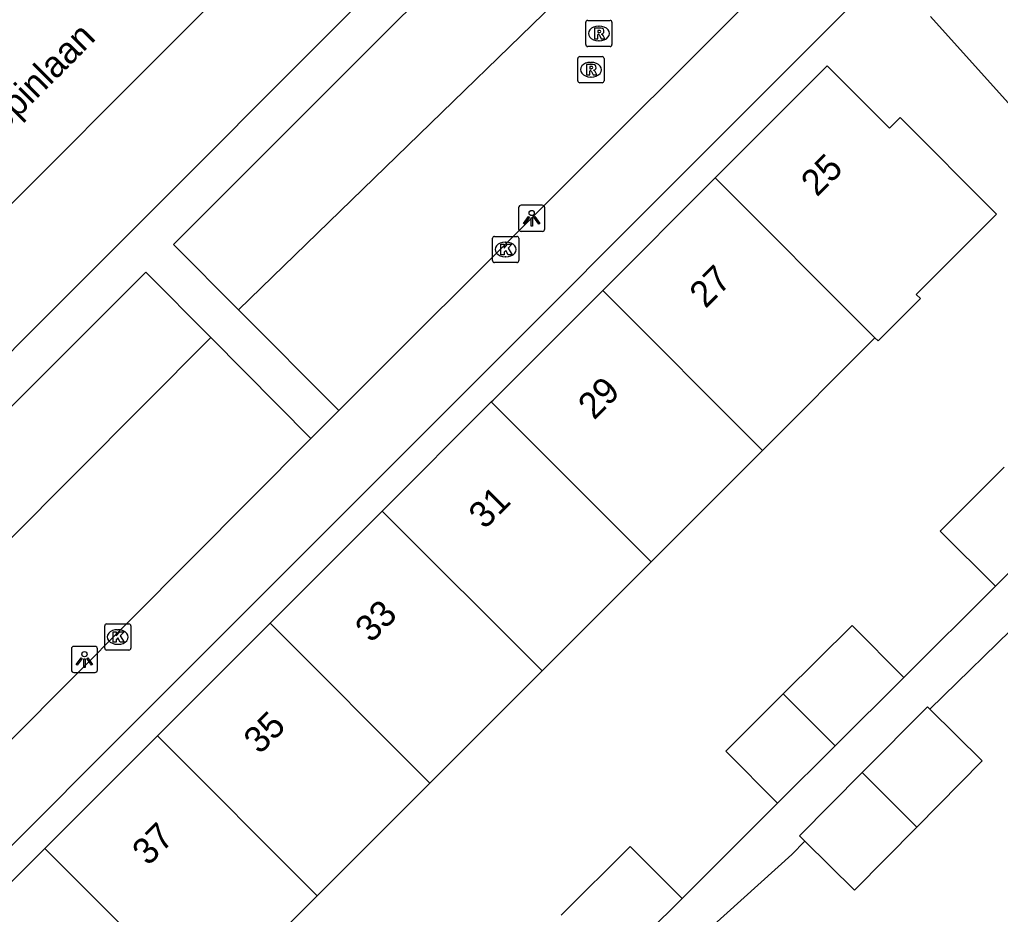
# Model space of a CAD drawing. Extents: x 159040 to 160094, y 381214 to 382518.
# Drawn here: x 159596.64 to 159634.1, y 381850.45 to 381884.61 of the extents above; entities that cross this region are included whole.
import ezdxf

# ---------------------------------------------------------------- set-up
doc = ezdxf.new("R2010")
doc.units = 0
for name, color, linetype in [('IMGEO_Groenvoorziening', 7, 'Continuous'), ('IMGEO_Kolk', 7, 'Continuous'), ('IMGEO_Lichtpunt', 7, 'Continuous'), ('IMGEO_Openbare_ruimte_label', 7, 'Continuous'), ('IMGEO_Pand', 7, 'Continuous'), ('IMGEO_Pand_nummerreeks', 7, 'Continuous'), ('IMGEO_Rijbaan_lokaal_open', 7, 'Continuous'), ('IMGEO_Rioolput', 7, 'Continuous'), ('IMGEO_Voetpad_open', 7, 'Continuous')]:
    doc.layers.add(name, color=color, linetype=linetype)

msp = doc.modelspace()

# ---------------------------------------------------------------- linework, layer by layer
at = {"layer": 'IMGEO_Groenvoorziening'}
for points in [[(159604.997, 381873.534), (159623.542, 381891.545)], [(159603.938, 381872.48), (159585.786, 381854.246)]]:
    msp.add_lwpolyline(points, dxfattribs=at)
at = {"layer": 'IMGEO_Kolk'}
for p, q in [((159614.699, 381875.411), (159614.699, 381876.263)), ((159614.774, 381876.337), (159615.626, 381876.337)), ((159615.187, 381876.117), (159615.212, 381876.117)), ((159615.7, 381876.263), (159615.7, 381875.411)), ((159615.626, 381875.337), (159614.774, 381875.337)), ((159615.21, 381875.557), (159615.185, 381875.557)), ((159599.887, 381860.615), (159599.887, 381861.467)), ((159599.962, 381861.541), (159600.814, 381861.541)), ((159600.888, 381861.467), (159600.888, 381860.615)), ((159600.375, 381861.321), (159600.4, 381861.321)), ((159600.398, 381860.761), (159600.373, 381860.761)), ((159600.814, 381860.541), (159599.962, 381860.541))]:
    msp.add_line(p, q, dxfattribs=at)
for points in [[(159614.699, 381875.411), (159614.699, 381876.263)], [(159614.774, 381876.337), (159615.626, 381876.337)], [(159615.7, 381876.263), (159615.7, 381875.411)], [(159615.02, 381876.037), (159615.143, 381876.037), (159615.143, 381875.886), (159615.273, 381876.037), (159615.437, 381876.037), (159615.291, 381875.886), (159615.444, 381875.637), (159615.292, 381875.637), (159615.207, 381875.801), (159615.143, 381875.734), (159615.143, 381875.637), (159615.02, 381875.637), (159615.02, 381876.037)], [(159615.626, 381875.337), (159614.774, 381875.337)], [(159599.887, 381860.615), (159599.887, 381861.467)], [(159599.962, 381861.541), (159600.814, 381861.541)], [(159600.888, 381861.467), (159600.888, 381860.615)], [(159600.208, 381861.241), (159600.331, 381861.241), (159600.331, 381861.09), (159600.461, 381861.241), (159600.625, 381861.241), (159600.479, 381861.09), (159600.632, 381860.841), (159600.48, 381860.841), (159600.395, 381861.005), (159600.331, 381860.938), (159600.331, 381860.841), (159600.208, 381860.841), (159600.208, 381861.241)], [(159600.814, 381860.541), (159599.962, 381860.541)]]:
    msp.add_lwpolyline(points, dxfattribs=at)
for centre, start, end in [((159614.776, 381876.261), 91.552, 178.448), ((159614.776, 381876.261), 91.552, 178.448), ((159615.624, 381876.261), 1.552, 88.448), ((159615.624, 381876.261), 1.552, 88.448), ((159614.776, 381875.413), 181.552, 268.448), ((159614.776, 381875.413), 181.552, 268.448), ((159615.624, 381875.413), 271.552, 358.448), ((159615.624, 381875.413), 271.552, 358.448), ((159599.964, 381861.465), 91.552, 178.448), ((159599.964, 381861.465), 91.552, 178.448), ((159600.812, 381861.465), 1.552, 88.448), ((159600.812, 381861.465), 1.552, 88.448), ((159599.964, 381860.617), 181.552, 268.448), ((159599.964, 381860.617), 181.552, 268.448), ((159600.812, 381860.617), 271.552, 358.448), ((159600.812, 381860.617), 271.552, 358.448)]:
    msp.add_arc(centre, 0.0765, start, end, dxfattribs=at)
for centre, major_axis, ratio, start_param, end_param in [((159615.186, 381875.837), (-0.387, 0.002), 0.722429, 4.712389, 7.853982), ((159615.211, 381875.837), (-0.39, 0.002), 0.717154, 1.570796, 4.712389), ((159600.374, 381861.041), (-0.387, 0.002), 0.722429, 4.712389, 7.853982), ((159600.399, 381861.041), (-0.39, 0.002), 0.717154, 1.570796, 4.712389)]:
    msp.add_ellipse(centre, major_axis=major_axis, ratio=ratio, start_param=start_param, end_param=end_param, dxfattribs=at)
at = {"layer": 'IMGEO_Lichtpunt'}
for p, q in [((159615.697, 381877.431), (159615.697, 381876.624)), ((159615.697, 381877.431), (159615.697, 381876.624)), ((159616.599, 381877.526), (159615.791, 381877.526)), ((159616.599, 381877.526), (159615.791, 381877.526)), ((159616.693, 381876.624), (159616.693, 381877.431)), ((159616.693, 381876.624), (159616.693, 381877.431)), ((159615.791, 381876.53), (159616.599, 381876.53)), ((159615.791, 381876.53), (159616.599, 381876.53)), ((159598.615, 381860.588), (159598.615, 381859.781)), ((159598.615, 381860.588), (159598.615, 381859.781)), ((159599.517, 381860.683), (159598.709, 381860.683)), ((159599.517, 381860.683), (159598.709, 381860.683)), ((159599.611, 381859.781), (159599.611, 381860.588)), ((159599.611, 381859.781), (159599.611, 381860.588)), ((159598.709, 381859.687), (159599.517, 381859.687)), ((159598.709, 381859.687), (159599.517, 381859.687))]:
    msp.add_line(p, q, dxfattribs=at)
for points in [[(159616.071, 381877.095), (159616.11, 381877.067), (159615.922, 381876.805), (159615.884, 381876.832), (159616.071, 381877.095)], [(159616.173, 381877.047), (159616.22, 381877.047), (159616.22, 381876.725), (159616.173, 381876.725), (159616.173, 381877.047)], [(159616.283, 381877.067), (159616.321, 381877.094), (159616.508, 381876.832), (159616.469, 381876.804), (159616.283, 381877.067)], [(159598.989, 381860.252), (159599.028, 381860.224), (159598.84, 381859.962), (159598.802, 381859.989), (159598.989, 381860.252)], [(159599.091, 381860.204), (159599.138, 381860.204), (159599.138, 381859.882), (159599.091, 381859.882), (159599.091, 381860.204)], [(159599.201, 381860.224), (159599.239, 381860.251), (159599.426, 381859.989), (159599.387, 381859.961), (159599.201, 381860.224)]]:
    msp.add_lwpolyline(points, dxfattribs=at)
for centre in [(159616.196, 381877.229), (159599.114, 381860.386)]:
    msp.add_circle(centre, 0.0994, dxfattribs=at)
for centre, start, end in [((159615.791, 381877.431), 90, 180), ((159615.791, 381877.431), 90, 180), ((159616.599, 381877.431), 0, 90), ((159616.599, 381877.431), 0, 90), ((159615.791, 381876.624), 180, 270), ((159615.791, 381876.624), 180, 270), ((159616.599, 381876.624), 270, 0), ((159616.599, 381876.624), 270, 360), ((159598.709, 381860.588), 90, 180), ((159598.709, 381860.588), 90, 180), ((159599.517, 381860.588), 0, 90), ((159599.517, 381860.588), 0, 90), ((159598.709, 381859.781), 180, 270), ((159598.709, 381859.781), 180, 270), ((159599.517, 381859.781), 270, 0), ((159599.517, 381859.781), 270, 360)]:
    msp.add_arc(centre, 0.0946, start, end, dxfattribs=at)
at = {"layer": 'IMGEO_Pand'}
for points in [[(159629.306, 381872.467), (159629.424, 381872.349), (159631.04, 381873.966), (159630.883, 381874.124), (159633.948, 381877.189), (159630.266, 381880.87), (159629.863, 381880.468), (159627.484, 381882.847), (159623.205, 381878.568)], [(159623.205, 381878.568), (159618.907, 381874.269)], [(159629.306, 381872.467), (159623.205, 381878.568)], [(159614.653, 381870.015), (159614.724, 381870.086), (159618.907, 381874.269)], [(159618.907, 381874.269), (159625.008, 381868.168)], [(159625.008, 381868.168), (159629.306, 381872.467)], [(159610.485, 381865.847), (159614.653, 381870.015)], [(159620.755, 381863.916), (159620.563, 381864.105), (159614.653, 381870.015)], [(159625.008, 381868.168), (159620.755, 381863.916)], [(159633.907, 381862.977), (159631.799, 381865.084), (159634.244, 381867.529)], [(159606.205, 381861.567), (159610.485, 381865.847)], [(159616.593, 381859.753), (159610.485, 381865.847)], [(159636.351, 381865.422), (159633.907, 381862.977)], [(159620.755, 381863.916), (159616.593, 381859.753)], [(159606.205, 381861.567), (159601.901, 381857.263)], [(159612.299, 381855.46), (159606.205, 381861.567)], [(159625.802, 381858.866), (159628.436, 381861.486), (159630.41, 381859.5)], [(159616.593, 381859.753), (159612.299, 381855.46)], [(159630.41, 381859.5), (159627.781, 381856.887)], [(159625.582, 381854.699), (159623.608, 381856.684), (159625.802, 381858.866)], [(159627.781, 381856.887), (159625.802, 381858.866)], [(159631.407, 381858.281), (159631.307, 381858.38), (159628.821, 381855.866)], [(159630.906, 381853.783), (159633.403, 381856.307), (159631.407, 381858.281)], [(159597.604, 381852.966), (159597.675, 381853.037), (159601.83, 381857.192), (159601.901, 381857.263)], [(159601.901, 381857.263), (159608.002, 381851.162)], [(159627.781, 381856.887), (159625.582, 381854.699)], [(159628.821, 381855.866), (159626.428, 381853.446), (159626.627, 381853.249)], [(159628.821, 381855.866), (159628.972, 381855.715), (159630.906, 381853.783)], [(159608.002, 381851.162), (159612.299, 381855.46)], [(159626.627, 381853.249), (159628.524, 381851.374), (159630.906, 381853.783)], [(159593.404, 381848.766), (159597.604, 381852.966)], [(159603.712, 381846.872), (159603.514, 381847.056), (159597.604, 381852.966)], [(159617.325, 381850.424), (159619.962, 381853.047), (159621.936, 381851.062)], [(159608.002, 381851.162), (159603.712, 381846.872)], [(159621.936, 381851.062), (159619.302, 381848.442)]]:
    msp.add_lwpolyline(points, dxfattribs=at)
at = {"layer": 'IMGEO_Rijbaan_lokaal_open'}
msp.add_lwpolyline([(159606.476, 381887.753), (159577.251, 381858.509)], dxfattribs=at)
at = {"layer": 'IMGEO_Rioolput'}
for p, q in [((159618.26, 381883.659), (159618.26, 381884.511)), ((159618.335, 381884.585), (159619.187, 381884.585)), ((159618.748, 381884.365), (159618.773, 381884.365)), ((159619.261, 381884.511), (159619.261, 381883.659)), ((159619.187, 381883.585), (159618.335, 381883.585)), ((159618.771, 381883.805), (159618.746, 381883.805)), ((159618.032, 381883.202), (159618.884, 381883.202)), ((159617.957, 381882.276), (159617.957, 381883.128)), ((159618.445, 381882.982), (159618.47, 381882.982)), ((159618.958, 381883.128), (159618.958, 381882.276)), ((159618.884, 381882.202), (159618.032, 381882.202)), ((159618.468, 381882.422), (159618.443, 381882.422))]:
    msp.add_line(p, q, dxfattribs=at)
for points in [[(159618.26, 381883.659), (159618.26, 381884.511)], [(159618.335, 381884.585), (159619.187, 381884.585)], [(159619.261, 381884.511), (159619.261, 381883.659)], [(159618.849, 381884.283), (159618.597, 381884.285), (159618.597, 381883.885)], [(159618.597, 381883.885), (159618.721, 381883.885), (159618.721, 381884.047), (159618.732, 381884.047)], [(159618.775, 381884.204), (159618.721, 381884.204), (159618.721, 381884.123)], [(159618.721, 381884.123), (159618.773, 381884.123)], [(159618.779, 381884.018), (159618.85, 381883.885), (159618.99, 381883.885), (159618.925, 381884.011)], [(159619.187, 381883.585), (159618.335, 381883.585)], [(159618.032, 381883.202), (159618.884, 381883.202)], [(159617.957, 381882.276), (159617.957, 381883.128)], [(159618.546, 381882.9), (159618.294, 381882.902), (159618.294, 381882.502)], [(159618.472, 381882.821), (159618.418, 381882.821), (159618.418, 381882.74)], [(159618.958, 381883.128), (159618.958, 381882.276)], [(159618.294, 381882.502), (159618.418, 381882.502), (159618.418, 381882.664), (159618.429, 381882.664)], [(159618.418, 381882.74), (159618.47, 381882.74)], [(159618.476, 381882.635), (159618.547, 381882.502), (159618.687, 381882.502), (159618.622, 381882.628)], [(159618.884, 381882.202), (159618.032, 381882.202)]]:
    msp.add_lwpolyline(points, dxfattribs=at)
for centre, radius, start, end in [((159618.337, 381884.509), 0.0765, 91.552, 178.448), ((159618.337, 381884.509), 0.0765, 91.552, 178.448), ((159619.185, 381884.509), 0.0765, 1.552, 88.448), ((159619.185, 381884.509), 0.0765, 1.552, 88.448), ((159618.731, 381883.994), 0.0533, 26.0293, 88.6989), ((159618.757, 381884.312), 0.19, 274.7715, 282.9687), ((159618.781, 381884.108), 0.0964, 77.0061, 93.1865), ((159618.795, 381884.165), 0.0378, 276.6634, 79.6772), ((159618.848, 381884.173), 0.109, 350.3612, 89.416), ((159618.846, 381884.173), 0.112, 277.5842, 350.9817), ((159618.83, 381883.958), 0.108, 29.5134, 73.7905), ((159618.337, 381883.661), 0.0765, 181.552, 268.448), ((159618.337, 381883.661), 0.0765, 181.552, 268.448), ((159619.185, 381883.661), 0.0765, 271.552, 358.448), ((159619.185, 381883.661), 0.0765, 271.552, 358.448), ((159618.034, 381883.126), 0.0765, 91.552, 178.448), ((159618.034, 381883.126), 0.0765, 91.552, 178.448), ((159618.882, 381883.126), 0.0765, 1.552, 88.448), ((159618.882, 381883.126), 0.0765, 1.552, 88.448), ((159618.478, 381882.725), 0.0964, 77.0061, 93.1865), ((159618.492, 381882.782), 0.0378, 276.6634, 79.6772), ((159618.545, 381882.79), 0.109, 350.3612, 89.416), ((159618.428, 381882.611), 0.0533, 26.0293, 88.6989), ((159618.454, 381882.929), 0.19, 274.7715, 282.9687), ((159618.543, 381882.79), 0.112, 277.5842, 350.9817), ((159618.527, 381882.575), 0.108, 29.5134, 73.7905), ((159618.034, 381882.278), 0.0765, 181.552, 268.448), ((159618.034, 381882.278), 0.0765, 181.552, 268.448), ((159618.882, 381882.278), 0.0765, 271.552, 358.448), ((159618.882, 381882.278), 0.0765, 271.552, 358.448)]:
    msp.add_arc(centre, radius, start, end, dxfattribs=at)
for centre, major_axis, ratio, start_param, end_param in [((159618.747, 381884.085), (-0.387, 0.002), 0.722429, 4.712389, 7.853982), ((159618.772, 381884.085), (-0.39, 0.002), 0.717154, 1.570796, 4.712389), ((159618.444, 381882.702), (-0.387, 0.002), 0.722429, 4.712389, 7.853982), ((159618.469, 381882.702), (-0.39, 0.002), 0.717154, 1.570796, 4.712389)]:
    msp.add_ellipse(centre, major_axis=major_axis, ratio=ratio, start_param=start_param, end_param=end_param, dxfattribs=at)
at = {"layer": 'IMGEO_Voetpad_open'}
for points in [[(159620.154, 381893.672), (159620.13, 381893.646), (159602.517, 381876.025), (159604.997, 381873.534)], [(159583.589, 381859.199), (159617.794, 381893.446)], [(159624.784, 381885.626), (159608.831, 381869.683)], [(159583.549, 381850.107), (159588.472, 381845.228), (159628.214, 381884.971)], [(159631.433, 381884.728), (159640.914, 381874.2)], [(159584.054, 381857.571), (159601.461, 381874.976), (159603.938, 381872.48)], [(159608.831, 381869.683), (159604.997, 381873.534)], [(159603.938, 381872.48), (159607.764, 381868.625)], [(159608.831, 381869.683), (159607.764, 381868.625)], [(159607.764, 381868.625), (159591.725, 381852.513)], [(159633.907, 381862.977), (159630.41, 381859.5)], [(159631.407, 381858.281), (159635.009, 381861.794)], [(159625.582, 381854.699), (159621.936, 381851.062)], [(159623.008, 381849.918), (159626.136, 381852.733), (159626.627, 381853.249)]]:
    msp.add_lwpolyline(points, dxfattribs=at)

# ---------------------------------------------------------------- texts
at = {"layer": 'IMGEO_Openbare_ruimte_label'}
msp.add_text('Chopinlaan', height=1, rotation=45, dxfattribs=at).set_placement((159594.805, 381879.089))
at = {"layer": 'IMGEO_Pand_nummerreeks'}
for s, rotation, p in [('25', 45.0001, (159627.09, 381877.814)), ('27', 45.0001, (159622.833, 381873.557)), ('29', 45.0006, (159618.576, 381869.301)), ('31', 45.0006, (159614.399, 381865.124)), ('33', 45.0006, (159610.063, 381860.787)), ('35', 45.0006, (159605.806, 381856.53)), ('37', 45.0006, (159601.549, 381852.273))]:
    msp.add_text(s, height=1, rotation=rotation, dxfattribs=at).set_placement(p)

doc.saveas('drawing.dxf')
